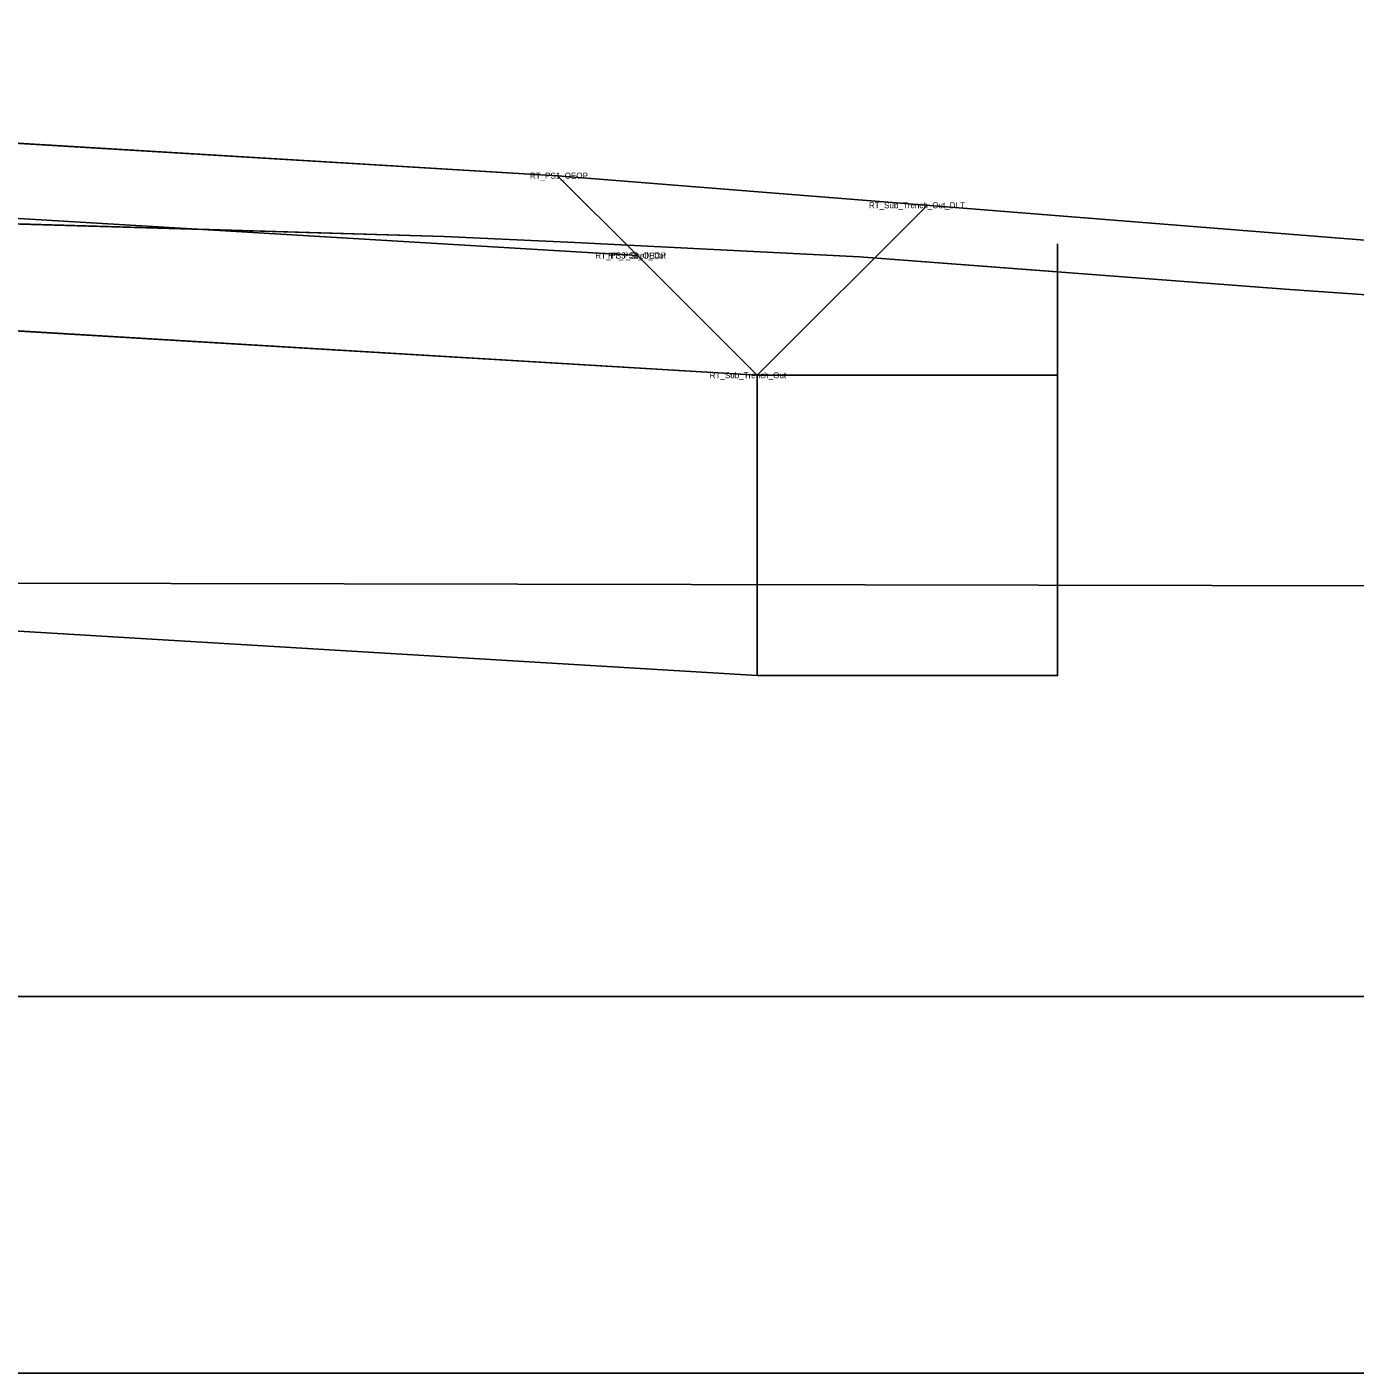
# Model space of a CAD drawing. Extents: x -516 to 303, y -10 to 5017.
# Drawn here: x 161.762 to 166.185, y 3500 to 3504.484 of the extents above; entities that cross this region are included whole.
import ezdxf

# ---------------------------------------------------------------- set-up
doc = ezdxf.new("R2010")
doc.units = 0
for name, color, linetype in [('Exist Cross Section Cell', 7, 'Continuous'), ('Exist XS Ground Line', 7, 'Continuous'), ('Prop CMT Pvmt Surface Shoulder', 7, 'Continuous'), ('Prop CMT Shld Paved Course 1', 7, 'Continuous'), ('Prop CMT Shld Paved Course 2', 7, 'Continuous'), ('Prop CMT Shld Paved Course 3', 7, 'Continuous'), ('Prop CMT Slope Grass', 7, 'Continuous'), ('Prop CMT Subgrade Earthwork', 7, 'Continuous'), ('Prop Road Sect_ Material - Contact (General - Major)', 7, 'Continuous'), ('Prop Road Sect_ Material - Contact (General - Minor)', 7, 'Continuous'), ('Prop Road Sect_ Misc - Drafting Aid (solid line)', 7, 'Continuous'), ('Prop Road Sect_ Recs - UC Shallow (Outline)', 7, 'Continuous'), ('Prop Road Sect_ Recs - UC Shallow (Pattern)', 7, 'Continuous'), ('Scratch_Level_0', 7, 'Continuous')]:
    doc.layers.add(name, color=color, linetype=linetype)

msp = doc.modelspace()

# ---------------------------------------------------------------- linework, layer by layer
at = {"layer": 'Exist Cross Section Cell'}
msp.add_line((150, 3500), (300, 3500), dxfattribs=at)
at = {"layer": 'Exist XS Ground Line'}
msp.add_lwpolyline([(125.205, 3503.8945), (131.7518, 3504.2176), (136.6829, 3504.4743), (138.318, 3504.4836), (148.612, 3504.249), (149.068, 3504.2286), (150, 3504.197), (151.3235, 3504.1521), (153.2258, 3504.1006), (154.2229, 3504.0743), (155.6813, 3504.0239), (157.1104, 3503.9729), (158.1124, 3503.9391), (159.3093, 3503.9003), (160.0118, 3503.8781), (163.151, 3503.7853), (163.5861, 3503.7651), (164.5345, 3503.7181), (165.9518, 3503.6102), (166.3074, 3503.5849)], dxfattribs=at)
at = {"layer": 'Prop CMT Pvmt Surface Shoulder'}
msp.add_line((161.5292, 3504.1082), (163.5292, 3503.9882), dxfattribs=at)
at = {"layer": 'Prop CMT Shld Paved Course 1'}
for points in [[(161.5292, 3504.1082), (163.5292, 3503.9882), (163.7952, 3503.7223)], [(163.7952, 3503.7223), (161.5292, 3503.8582)]]:
    msp.add_lwpolyline(points, dxfattribs=at)
at = {"layer": 'Prop CMT Shld Paved Course 2'}
for points in [[(161.5292, 3503.8582), (163.7952, 3503.7223)], [(163.7952, 3503.7223), (161.5292, 3503.8582)], [(163.7952, 3503.7223), (163.7952, 3503.7223)]]:
    msp.add_lwpolyline(points, dxfattribs=at)
at = {"layer": 'Prop CMT Shld Paved Course 3'}
for points in [[(161.5292, 3503.8582), (163.7952, 3503.7223)], [(163.7952, 3503.7223), (163.7952, 3503.7223)], [(163.7952, 3503.7223), (164.1941, 3503.3234)], [(164.1941, 3503.3234), (161.5292, 3503.4832)]]:
    msp.add_lwpolyline(points, dxfattribs=at)
at = {"layer": 'Prop CMT Slope Grass'}
msp.add_line((163.5292, 3503.9882), (170, 3503.4706), dxfattribs=at)
at = {"layer": 'Prop CMT Subgrade Earthwork'}
for p, q in [((164.1941, 3503.3234), (164.7605, 3503.8897)), ((161.5292, 3503.4832), (164.1941, 3503.3234))]:
    msp.add_line(p, q, dxfattribs=at)
at = {"layer": 'Prop Road Sect_ Material - Contact (General - Major)'}
msp.add_line((176.8467, 3502.6017), (116.479, 3502.7189), dxfattribs=at)
at = {"layer": 'Prop Road Sect_ Material - Contact (General - Minor)'}
msp.add_line((112.3685, 3501.2539), (189.7041, 3501.2539), dxfattribs=at)
at = {"layer": 'Prop Road Sect_ Misc - Drafting Aid (solid line)'}
for p, q in [((165.1941, 3503.3234), (165.1941, 3503.7617)), ((164.1941, 3503.3234), (164.1941, 3502.3234)), ((164.1941, 3503.3234), (165.1941, 3503.3234)), ((165.1941, 3502.3234), (165.1941, 3503.3234)), ((164.1941, 3502.3234), (165.1941, 3502.3234))]:
    msp.add_line(p, q, dxfattribs=at)
at = {"layer": 'Prop Road Sect_ Recs - UC Shallow (Outline)'}
msp.add_lwpolyline([(165.1941, 3503.3234), (165.1941, 3503.6679), (164.5345, 3503.7181), (163.5861, 3503.7651), (163.151, 3503.7853), (159.3093, 3503.9003), (158.1124, 3503.9391), (157.1104, 3503.9729), (155.6813, 3504.0239), (154.2229, 3504.0743), (151.3235, 3504.1521), (150, 3504.197), (149.068, 3504.2286), (148.612, 3504.249), (148.0014, 3504.2629), (145.4104, 3504.322), (145.4104, 3503.4504), (148, 3503.295), (161.5292, 3502.4832), (164.1941, 3502.3234), (165.1941, 3502.3234), (165.1941, 3503.3234)], dxfattribs=at)
at = {"layer": 'Prop Road Sect_ Recs - UC Shallow (Pattern)'}
msp.add_lwpolyline([(165.1941, 3503.3234), (165.1941, 3503.6679), (164.5345, 3503.7181), (163.5861, 3503.7651), (163.151, 3503.7853), (159.3093, 3503.9003), (158.1124, 3503.9391), (157.1104, 3503.9729), (155.6813, 3504.0239), (154.2229, 3504.0743), (151.3235, 3504.1521), (150, 3504.197), (149.068, 3504.2286), (148.612, 3504.249), (148.0014, 3504.2629), (145.4104, 3504.322), (145.4104, 3503.4504), (148, 3503.295), (161.5292, 3502.4832), (164.1941, 3502.3234), (165.1941, 3502.3234), (165.1941, 3503.3234)], dxfattribs=at)

# ---------------------------------------------------------------- texts
at = {"layer": 'Scratch_Level_0'}
for s, p in [('RT_PS1_OEOP', (163.4368, 3503.9782)), ('RT_Sub_Trench_Out_DLT', (164.5657, 3503.8797)), ('RT_PS3_Shelf_Out', (163.6545, 3503.7123)), ('RT_PS3_OEOP', (163.697, 3503.7123)), ('RT_PS2_OEOP', (163.697, 3503.7123)), ('RT_Sub_Trench_Out', (164.0357, 3503.3134))]:
    msp.add_text(s, height=0.02, dxfattribs=at).set_placement(p)

doc.saveas('drawing.dxf')
